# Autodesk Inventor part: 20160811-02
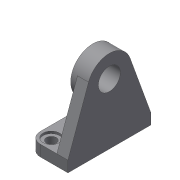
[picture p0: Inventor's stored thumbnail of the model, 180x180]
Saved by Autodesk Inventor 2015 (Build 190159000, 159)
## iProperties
Created: 2016-08
Part Number: 20160811-02
Material: Hliník 6061
Document SubType Name: Modeling
Designer: navara
Density: 2.7 g/cm^3
Appearance: Hliník – plochý
Beppe: 20160811-02.ipt
Author: navara
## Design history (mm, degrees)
sketch "Náčrt1"
  geometry: L1 (-37.5, 0)-(37.5, 0); L2 (37.5, 0)-(37.5, 10); L3 (37.5, 10)-(18.813, 61.788); L4 (-18.813, 61.788)-(-37.5, 10); L5 (-37.5, 10)-(-37.5, 0); A1 r 20 centre (0, 55) between (18.813, 61.788) and (-18.813, 61.788); 2 further points
  constraints: 10 end point, 2 equal length, 2 perpendicular, 2 point on circle, 2 tangent, 1 centre point, 1 coincident, 1 horizontal, 1 midpoint
  dimensions: "d0" = 75 dimension on A1 L1; "d1" = 20 radius of A1; "d2" = 10 distance of L4.end L1.start; "d3" = 75 distance of L1.start L1.end
extrude "Vysunutí1" new body sketch "Náčrt1" distance "d4" = 10; taper "d5" = 0 deg
sketch "Náčrt2"
  geometry: L1 (0, -37.5)-(-10, -37.5); L2 (-10, -37.5)-(-10, 37.5); L3 (-10, 37.5)-(0, 37.5); L4 (0, 37.5)-(0, -37.5)
  constraints: 8 end point, 2 parallel, 1 horizontal, 1 perpendicular
extrude "Vysunutí2" join sketch "Náčrt2" distance "d6" = 35; taper "d7" = 0 deg
sketch "Náčrt3"
  geometry: C1 r 20 at (-55, 0); A1 r 20 centre (-55, 0) between (-61.788, 18.813) and (-61.788, -18.813) reference
  constraints: 1 centre point, 1 coincident, 1 concentric
extrude "Vysunutí3" join sketch "Náčrt3" distance "d8" = 15; taper "d9" = 0 deg
hole "Díra1" diameter "d12" = 20; stored, may be unused: countersink angle "d16" = 90 deg, drill point angle "d18" = 118 deg; dims "d13" = 6, "d14" = 4, "d15" = 2, "d17" = 8, "d27" = 10, "d28" = 10
fillet "Zaoblení1" dims "d19" = 10
sketch "Náčrt4"
  geometry: L1 (-25, 10)-(-25, 65) reference; L2 (0, 0)-(-15, 0) reference; L3 (0, 75)-(0, 0) reference; L4 (0, 75)-(-15, 75) reference; A1 r 10 centre (-15, 65) between (-15, 75) and (-25, 65) reference; A2 r 10 centre (-15, 10) between (-25, 10) and (-15, 0) reference
hole "Díra2" sketch "Náčrt4" at (-15, 65), (-15, 10) diameter "d20" = 9; stored, may be unused: countersink angle "d24" = 90 deg, drill point angle "d26" = 118 deg; dims "d21" = 6, "d22" = 15, "d23" = 2, "d25" = 8
node "Těleso1"
node "Promítnutá smyčka1"
